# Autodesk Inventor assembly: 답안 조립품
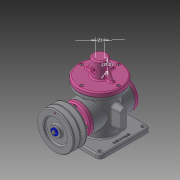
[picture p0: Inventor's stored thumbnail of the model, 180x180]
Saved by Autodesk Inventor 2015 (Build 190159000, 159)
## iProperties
Created: 2020-02
Part Number: 답안 조립품
Document SubType Name: Assembly
Designer: LINEART-A501
Author: LINEART-A501
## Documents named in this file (21)
- C:\Users\LINEART-A501\Desktop\600206V1025\답안 조립품.iam
- C:\Users\LINEART-A501\Desktop\600206V1025\본체.ipt
- C:\Users\LINEART-A501\Desktop\600206V1025\앞커버.ipt
- C:\Users\LINEART-A501\Desktop\600206V1025\뒤커버.ipt
- C:\Users\LINEART-A501\Desktop\600206V1025\개스킷 A.ipt
- C:\Users\LINEART-A501\Desktop\600206V1025\육각 소켓 머리 볼트 M4 x 10.ipt
- C:\Users\LINEART-A501\Desktop\600206V1025\베어링 17 x 40 x 12.ipt
- C:\Users\LINEART-A501\Desktop\600206V1025\편심축.ipt
- C:\Users\LINEART-A501\Desktop\600206V1025\키 4 x 4 x 25.ipt
- C:\Users\LINEART-A501\Desktop\600206V1025\V-벨트풀리.ipt
- C:\Users\LINEART-A501\Desktop\600206V1025\와셔 4x16.ipt
- C:\Users\LINEART-A501\Desktop\600206V1025\볼트 M4 x 10.ipt
- C:\Users\LINEART-A501\Desktop\600206V1025\링크.ipt
- C:\Users\LINEART-A501\Desktop\600206V1025\슬라이더.ipt
- C:\Users\LINEART-A501\Desktop\600206V1025\클레비스 핀 6 x 22.ipt
- 클레비스 핀 6 x 22.ipt
- C:\Users\LINEART-A501\Desktop\600206V1025\E-링.ipt
- C:\Users\LINEART-A501\Desktop\600206V1025\가변 스프링.ipt
- C:\Users\LINEART-A501\Desktop\600206V1025\개스킷 B.ipt
- C:\Users\LINEART-A501\Desktop\600206V1025\덮개.ipt
- C:\Users\LINEART-A501\Desktop\600206V1025\오일 실 17 30 8.ipt
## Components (6 placed, 5 different names)
1. 개스킷 A:1
2. 개스킷 A:2
3. V-벨트풀리:1 — 각도:4, 플러쉬:3
4. E-링:1
5. 가변 스프링:1
6. 개스킷 B:1
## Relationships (2: Angle 1, Flush 1)
- 각도:4 [Angle]: V-벨트풀리:1
- 플러쉬:3 [Flush]: V-벨트풀리:1
